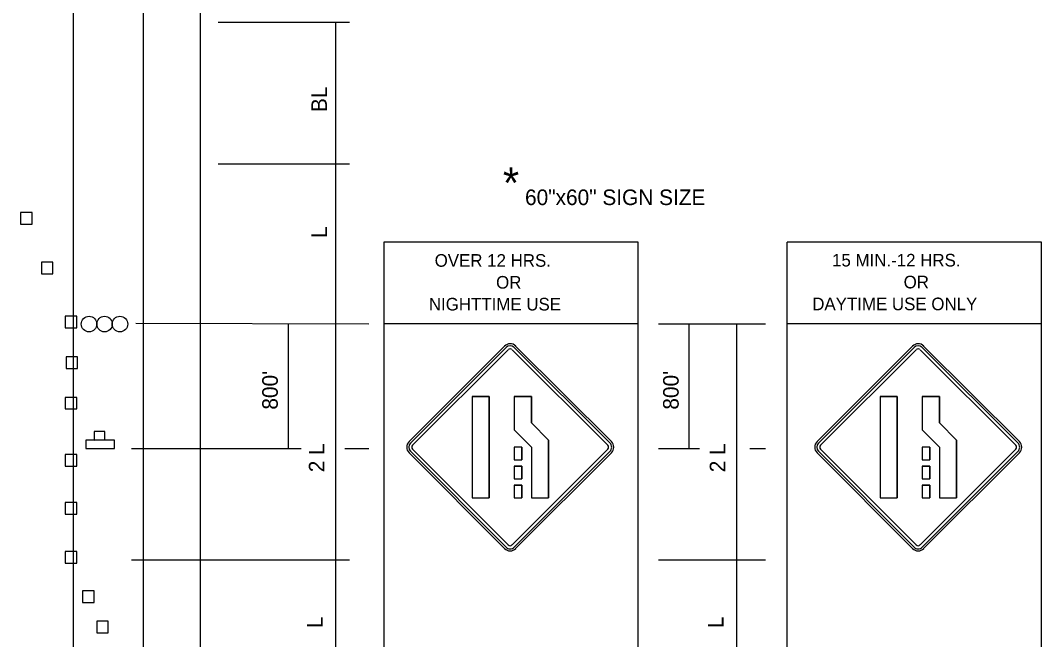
# Model space of a CAD drawing. Extents: x 1531.3 to 1538.6, y 1529.6 to 1539.7.
# Drawn here: x 1534.458 to 1538.391, y 1535.19 to 1537.574 of the extents above; entities that cross this region are included whole.
import ezdxf

# ---------------------------------------------------------------- set-up
doc = ezdxf.new("R2010")
doc.units = 0
for name, color, linetype in [('DETL-DIMS', 7, 'Continuous'), ('DETL-LINE', 7, 'Continuous'), ('DETL-NOTE', 7, 'Continuous'), ('USER-BORD', 7, 'Continuous')]:
    doc.layers.add(name, color=color, linetype=linetype)

# ---------------------------------------------------------------- blocks, each defined once
blk = doc.blocks.new('PANEL0')
at = {"layer": 'USER-BORD'}
for centre in [(0.00309, -0.00012), (0.00928, -0.00012), (0.01546, -0.00012)]:
    blk.add_circle(centre, 0.00312, dxfattribs=at)
blk = doc.blocks.new('SIGN15')
at = {"layer": 'USER-BORD'}
for points in [[(-0.0013, 0.0018), (0.0011, 0.0019), (0.0011, 0.0037), (-0.0013, 0.0037)], [(-0.0031, 0.0018), (-0.0031, 0), (0.0032, 0), (0.0032, 0.0018)]]:
    blk.add_lwpolyline(points, close=True, dxfattribs=at)

msp = doc.modelspace()

# ---------------------------------------------------------------- linework, layer by layer
at = {"layer": 'DETL-DIMS'}
for p, q in [((1535.2198, 1537.5673), (1535.7247, 1537.5673)), ((1535.6719, 1537.5673), (1535.6719, 1535.4966)), ((1535.2198, 1537.022), (1535.7247, 1537.022)), ((1534.9019, 1536.4076), (1535.7998, 1536.4049)), ((1535.4886, 1536.4057), (1535.4886, 1535.9254)), ((1536.9152, 1536.4047), (1537.3272, 1536.4047)), ((1537.0325, 1536.4057), (1537.0325, 1535.9254)), ((1537.2158, 1536.4047), (1537.2158, 1535.4966)), ((1534.8858, 1535.9254), (1535.5393, 1535.9254)), ((1535.7071, 1535.9254), (1535.7998, 1535.9254)), ((1536.9152, 1535.9254), (1537.0727, 1535.9254)), ((1537.2667, 1535.9254), (1537.3272, 1535.9254)), ((1534.8858, 1535.4966), (1535.7247, 1535.4966)), ((1535.6719, 1535.4966), (1535.6719, 1534.9729)), ((1536.9152, 1535.4966), (1537.3272, 1535.4966)), ((1537.2158, 1535.4966), (1537.2158, 1534.9729)), ((1535.6719, 1535.3867), (1535.6719, 1535.3775)), ((1537.2158, 1535.3867), (1537.2158, 1535.3775))]:
    msp.add_line(p, q, dxfattribs=at)
at = {"layer": 'DETL-LINE'}
for p, q in [((1534.6611, 1539.3543), (1534.6611, 1531.4117)), ((1534.9308, 1539.3543), (1534.9308, 1531.4117)), ((1535.1507, 1539.3543), (1535.1507, 1531.4117)), ((1536.8376, 1536.7193), (1535.8576, 1536.7193)), ((1535.8576, 1536.7193), (1535.8576, 1531.1028)), ((1536.8376, 1531.1028), (1536.8376, 1536.7193)), ((1537.4108, 1531.9687), (1537.4108, 1536.7193)), ((1538.3907, 1536.7193), (1537.4108, 1536.7193)), ((1538.3907, 1531.9687), (1538.3907, 1536.7193)), ((1536.8376, 1536.4047), (1535.8576, 1536.4047)), ((1538.3907, 1536.4047), (1537.4108, 1536.4047)), ((1535.9544, 1535.9517), (1536.3226, 1536.3198)), ((1535.9599, 1535.9462), (1536.328, 1536.3144)), ((1535.9684, 1535.9377), (1536.3365, 1536.3058)), ((1536.3512, 1536.3058), (1536.7201, 1535.9377)), ((1536.3598, 1536.3144), (1536.7287, 1535.9462)), ((1536.3652, 1536.3198), (1536.7341, 1535.9517)), ((1537.5258, 1535.9517), (1537.894, 1536.3198)), ((1537.5313, 1535.9462), (1537.8994, 1536.3144)), ((1537.5398, 1535.9377), (1537.9079, 1536.3058)), ((1537.9226, 1536.3058), (1538.2915, 1535.9377)), ((1537.9312, 1536.3144), (1538.3001, 1535.9462)), ((1537.9366, 1536.3198), (1538.3055, 1535.9517)), ((1536.1974, 1536.1257), (1536.1974, 1535.735)), ((1536.1974, 1536.1257), (1536.263, 1536.1257)), ((1536.263, 1536.1257), (1536.1974, 1536.1257)), ((1536.1974, 1536.1257), (1536.1974, 1535.735)), ((1536.263, 1536.1257), (1536.263, 1535.735)), ((1536.263, 1535.735), (1536.263, 1536.1257)), ((1536.3599, 1536.1257), (1536.3599, 1535.9968)), ((1536.3599, 1536.1257), (1536.4256, 1536.1257)), ((1536.4256, 1536.1257), (1536.3599, 1536.1257)), ((1536.3599, 1536.1257), (1536.3599, 1535.9968)), ((1536.4256, 1536.1257), (1536.4256, 1536.0239)), ((1536.4256, 1536.0239), (1536.4256, 1536.1257)), ((1537.7688, 1536.1257), (1537.7688, 1535.735)), ((1537.7688, 1536.1257), (1537.8344, 1536.1257)), ((1537.8344, 1536.1257), (1537.7688, 1536.1257)), ((1537.7688, 1536.1257), (1537.7688, 1535.735)), ((1537.8344, 1536.1257), (1537.8344, 1535.735)), ((1537.8344, 1535.735), (1537.8344, 1536.1257)), ((1537.9313, 1536.1257), (1537.9313, 1535.9968)), ((1537.9313, 1536.1257), (1537.997, 1536.1257)), ((1537.997, 1536.1257), (1537.9313, 1536.1257)), ((1537.9313, 1536.1257), (1537.9313, 1535.9968)), ((1537.997, 1536.1257), (1537.997, 1536.0239)), ((1537.997, 1536.0239), (1537.997, 1536.1257)), ((1536.492, 1535.9576), (1536.4256, 1536.0239)), ((1536.492, 1535.9576), (1536.4256, 1536.0239)), ((1538.0634, 1535.9576), (1537.997, 1536.0239)), ((1538.0634, 1535.9576), (1537.997, 1536.0239)), ((1536.4263, 1535.9304), (1536.3599, 1535.9968)), ((1536.3599, 1535.9968), (1536.4263, 1535.9304)), ((1537.9977, 1535.9304), (1537.9313, 1535.9968)), ((1537.9313, 1535.9968), (1537.9977, 1535.9304)), ((1536.492, 1535.9576), (1536.492, 1535.735)), ((1536.492, 1535.735), (1536.492, 1535.9576)), ((1538.0634, 1535.9576), (1538.0634, 1535.735)), ((1538.0634, 1535.735), (1538.0634, 1535.9576)), ((1536.3226, 1535.5401), (1535.9544, 1535.909)), ((1536.328, 1535.5456), (1535.9599, 1535.9145)), ((1536.3365, 1535.5541), (1535.9684, 1535.923)), ((1536.7201, 1535.923), (1536.3512, 1535.5541)), ((1536.7287, 1535.9145), (1536.3598, 1535.5456)), ((1536.3599, 1535.9304), (1536.3599, 1535.8815)), ((1536.3889, 1535.9304), (1536.3599, 1535.9304)), ((1536.3599, 1535.9304), (1536.3599, 1535.8815)), ((1536.7341, 1535.909), (1536.3652, 1535.5401)), ((1536.3889, 1535.9304), (1536.3889, 1535.8815)), ((1536.3889, 1535.8815), (1536.3889, 1535.9304)), ((1536.4263, 1535.9304), (1536.4263, 1535.735)), ((1536.4263, 1535.9304), (1536.4263, 1535.735)), ((1537.894, 1535.5401), (1537.5258, 1535.909)), ((1537.8994, 1535.5456), (1537.5313, 1535.9145)), ((1537.9079, 1535.5541), (1537.5398, 1535.923)), ((1538.2915, 1535.923), (1537.9226, 1535.5541)), ((1538.3001, 1535.9145), (1537.9312, 1535.5456)), ((1537.9313, 1535.9304), (1537.9313, 1535.8815)), ((1537.9603, 1535.9304), (1537.9313, 1535.9304)), ((1537.9313, 1535.9304), (1537.9313, 1535.8815)), ((1538.3055, 1535.909), (1537.9366, 1535.5401)), ((1537.9603, 1535.9304), (1537.9603, 1535.8815)), ((1537.9603, 1535.8815), (1537.9603, 1535.9304)), ((1537.9977, 1535.9304), (1537.9977, 1535.735)), ((1537.9977, 1535.9304), (1537.9977, 1535.735)), ((1536.3599, 1535.8815), (1536.3889, 1535.8815)), ((1536.3599, 1535.8815), (1536.3889, 1535.8815)), ((1536.3599, 1535.8571), (1536.3889, 1535.8571)), ((1536.3599, 1535.8571), (1536.3599, 1535.8083)), ((1536.3889, 1535.8571), (1536.3599, 1535.8571)), ((1536.3599, 1535.8571), (1536.3599, 1535.8083)), ((1536.3889, 1535.8571), (1536.3889, 1535.8083)), ((1536.3889, 1535.8083), (1536.3889, 1535.8571)), ((1537.9313, 1535.8815), (1537.9603, 1535.8815)), ((1537.9313, 1535.8815), (1537.9603, 1535.8815)), ((1537.9313, 1535.8571), (1537.9603, 1535.8571)), ((1537.9313, 1535.8571), (1537.9313, 1535.8083)), ((1537.9603, 1535.8571), (1537.9313, 1535.8571)), ((1537.9313, 1535.8571), (1537.9313, 1535.8083)), ((1537.9603, 1535.8571), (1537.9603, 1535.8083)), ((1537.9603, 1535.8083), (1537.9603, 1535.8571)), ((1536.3599, 1535.8083), (1536.3889, 1535.8083)), ((1536.3599, 1535.8083), (1536.3889, 1535.8083)), ((1536.3599, 1535.7839), (1536.3889, 1535.7839)), ((1536.3599, 1535.7839), (1536.3599, 1535.735)), ((1536.3889, 1535.7839), (1536.3599, 1535.7839)), ((1536.3599, 1535.7839), (1536.3599, 1535.735)), ((1536.3889, 1535.7839), (1536.3889, 1535.735)), ((1536.3889, 1535.735), (1536.3889, 1535.7839)), ((1537.9313, 1535.8083), (1537.9603, 1535.8083)), ((1537.9313, 1535.8083), (1537.9603, 1535.8083)), ((1537.9313, 1535.7839), (1537.9603, 1535.7839)), ((1537.9313, 1535.7839), (1537.9313, 1535.735)), ((1537.9603, 1535.7839), (1537.9313, 1535.7839)), ((1537.9313, 1535.7839), (1537.9313, 1535.735)), ((1537.9603, 1535.7839), (1537.9603, 1535.735)), ((1537.9603, 1535.735), (1537.9603, 1535.7839)), ((1536.1974, 1535.735), (1536.263, 1535.735)), ((1536.1974, 1535.735), (1536.263, 1535.735)), ((1536.3599, 1535.735), (1536.3889, 1535.735)), ((1536.3599, 1535.735), (1536.3889, 1535.735)), ((1536.4263, 1535.735), (1536.492, 1535.735)), ((1536.4263, 1535.735), (1536.492, 1535.735)), ((1537.7688, 1535.735), (1537.8344, 1535.735)), ((1537.7688, 1535.735), (1537.8344, 1535.735)), ((1537.9313, 1535.735), (1537.9603, 1535.735)), ((1537.9313, 1535.735), (1537.9603, 1535.735)), ((1537.9977, 1535.735), (1538.0634, 1535.735)), ((1537.9977, 1535.735), (1538.0634, 1535.735))]:
    msp.add_line(p, q, dxfattribs=at)
for points in [[(1534.4578, 1536.7897), (1534.5026, 1536.7897), (1534.5026, 1536.8345), (1534.4578, 1536.8345)], [(1534.5384, 1536.5977), (1534.5832, 1536.5977), (1534.5832, 1536.6425), (1534.5384, 1536.6425)], [(1534.6306, 1536.3903), (1534.6754, 1536.3903), (1534.6754, 1536.4351), (1534.6306, 1536.4351)], [(1534.6334, 1536.2329), (1534.6782, 1536.2329), (1534.6782, 1536.2777), (1534.6334, 1536.2777)], [(1534.6306, 1536.0774), (1534.6754, 1536.0774), (1534.6754, 1536.1222), (1534.6306, 1536.1222)], [(1534.6306, 1535.8575), (1534.6754, 1535.8575), (1534.6754, 1535.9023), (1534.6306, 1535.9023)], [(1534.6306, 1535.6722), (1534.6754, 1535.6722), (1534.6754, 1535.717), (1534.6306, 1535.717)], [(1534.6306, 1535.4841), (1534.6754, 1535.4841), (1534.6754, 1535.5289), (1534.6306, 1535.5289)], [(1534.6974, 1535.332), (1534.7422, 1535.332), (1534.7422, 1535.3768), (1534.6974, 1535.3768)], [(1534.7515, 1535.2151), (1534.7963, 1535.2151), (1534.7963, 1535.2599), (1534.7515, 1535.2599)]]:
    msp.add_lwpolyline(points, close=True, dxfattribs=at)
for centre, radius, start, end in [((1536.3439, 1536.2983), 0.0303, 45.06, 135), ((1537.9153, 1536.2983), 0.0303, 45.06, 135), ((1536.3439, 1536.2988), 0.0223, 45.06, 135), ((1536.3439, 1536.2989), 0.0101, 45.06, 135), ((1537.9153, 1536.2988), 0.0223, 45.06, 135), ((1537.9153, 1536.2989), 0.0101, 45.06, 135), ((1535.9759, 1535.9304), 0.0303, 135, 224.9399), ((1535.9755, 1535.9304), 0.0223, 135, 224.9399), ((1535.9753, 1535.9304), 0.0101, 135, 224.9399), ((1536.7132, 1535.9304), 0.0101, 315, 45.0601), ((1536.713, 1535.9304), 0.0223, 315, 45.0601), ((1536.7126, 1535.9304), 0.0303, 315, 45.0601), ((1537.5473, 1535.9304), 0.0303, 135, 224.9399), ((1537.5469, 1535.9304), 0.0223, 135, 224.9399), ((1537.5467, 1535.9304), 0.0101, 135, 224.9399), ((1538.2846, 1535.9304), 0.0101, 315, 45.0601), ((1538.2844, 1535.9304), 0.0223, 315, 45.0601), ((1538.284, 1535.9304), 0.0303, 315, 45.0601), ((1536.3439, 1535.5616), 0.0303, 224.94, 315), ((1536.3439, 1535.5612), 0.0223, 224.94, 315), ((1536.3439, 1535.561), 0.0101, 224.94, 315), ((1537.9153, 1535.5616), 0.0303, 224.94, 315), ((1537.9153, 1535.5612), 0.0223, 224.94, 315), ((1537.9153, 1535.561), 0.0101, 224.94, 315)]:
    msp.add_arc(centre, radius, start, end, dxfattribs=at)

# ---------------------------------------------------------------- block references
for name, p, xscale, yscale in [('PANEL0', (1534.6926, 1536.4055), 9.6, 9.6), ('SIGN15', (1534.7642, 1535.9257), 17.523809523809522, 17.523809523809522)]:
    msp.add_blockref(name, p, dxfattribs=dict(at, xscale=xscale, yscale=yscale))

# ---------------------------------------------------------------- texts
for s, p in [('OVER 12 HRS.', (1536.0533, 1536.6251)), ('15 MIN.-12 HRS.', (1537.5838, 1536.6261)), ('OR', (1536.2898, 1536.5409)), ('OR', (1537.8595, 1536.5419)), ('NIGHTTIME USE', (1536.0308, 1536.4567)), ('DAYTIME USE ONLY', (1537.5075, 1536.4577))]:
    msp.add_text(s, height=0.0486, dxfattribs=at).set_placement(p)
at = {"layer": 'DETL-NOTE'}
for s, p in [('BL', (1535.6383, 1537.2208)), ('L', (1535.6383, 1536.7362)), ("800'", (1535.4491, 1536.0749)), ("800'", (1536.993, 1536.0749)), ('2 L', (1535.6287, 1535.8338)), ('2 L', (1537.1726, 1535.8338)), ('L', (1535.622, 1535.2338)), ('L', (1537.1659, 1535.2338))]:
    msp.add_text(s, height=0.06, rotation=90, dxfattribs=at).set_placement(p)
for s, height, p in [('*', 0.12, (1536.3161, 1536.8881)), ('60"x60" SIGN SIZE', 0.06, (1536.4013, 1536.8626))]:
    msp.add_text(s, height=height, dxfattribs=at).set_placement(p)

doc.saveas('drawing.dxf')
